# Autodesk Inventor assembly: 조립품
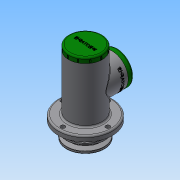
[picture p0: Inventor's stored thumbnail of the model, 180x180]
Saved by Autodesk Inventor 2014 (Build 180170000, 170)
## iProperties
Created: 2016-08
Part Number: 조립품
Document SubType Name: Assembly
Designer: NET
Author: NET
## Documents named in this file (25)
- C:\Users\NET\Desktop\460807V1020\460807V1020\조립품.iam
- C:\Users\NET\Desktop\460807V1020\460807V1020\부품.ipt
- C:\Users\NET\Desktop\460807V1020\460807V1020\편심축.ipt
- C:\Users\NET\Desktop\460807V1020\460807V1020\링크.ipt
- C:\Users\NET\Desktop\460807V1020\460807V1020\클래스터 핀 6 x 24.ipt
- C:\Users\NET\Desktop\460807V1020\460807V1020\분할핀 1.6 x 12.ipt
- C:\Users\NET\Desktop\460807V1020\460807V1020\슬라이더.ipt
- C:\Users\NET\Desktop\460807V1020\460807V1020\탑 커버.ipt
- 탑 커버.ipt
- C:\Users\NET\Desktop\460807V1020\460807V1020\탑 부시.ipt
- C:\Users\NET\Desktop\460807V1020\460807V1020\사이드 커버.ipt
- 사이드 커버.ipt
- C:\Users\NET\Desktop\460807V1020\460807V1020\볼트 M4 x 12.ipt
- C:\Users\NET\Desktop\460807V1020\460807V1020\베어링 15 x 35 x 11.ipt
- C:\Users\NET\Desktop\460807V1020\460807V1020\부시1.ipt
- C:\Users\NET\Desktop\460807V1020\460807V1020\오일 실 15 25 7.ipt
- C:\Users\NET\Desktop\460807V1020\460807V1020\V-벨트풀리.ipt
- C:\Users\NET\Desktop\460807V1020\460807V1020\키 4 x 4 x 18.ipt
- C:\Users\NET\Desktop\460807V1020\460807V1020\와셔 4x16.ipt
- C:\Users\NET\Desktop\460807V1020\460807V1020\볼트 M4 x 10.ipt
- C:\Users\NET\Desktop\460807V1020\460807V1020\멈춤링 15 x 1.ipt
- C:\Users\NET\Desktop\460807V1020\460807V1020\멈춤링 35x1.6.ipt
- C:\Users\NET\Desktop\460807V1020\460807V1020\부시2.ipt
- C:\Users\NET\Desktop\460807V1020\460807V1020\와셔 10x21.ipt
- C:\Users\NET\Desktop\460807V1020\460807V1020\너트 M10.ipt
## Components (6 placed, 3 different names)
1. V-벨트풀리:1
2. ISO 4017 M4 x 10:1
3. ISO 4762 M4 x 12:1
4. ISO 4762 M4 x 12:2
5. ISO 4762 M4 x 12:3
6. ISO 4762 M4 x 12:4
